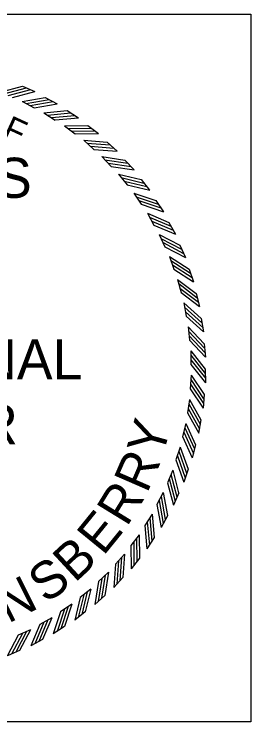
# Model space of a CAD drawing. Extents: x 164 to 3385, y 68 to 2119.
# Drawn here: x 3177.5 to 3264.9, y 441.7 to 702.4 of the extents above; entities that cross this region are included whole.
import ezdxf

# ---------------------------------------------------------------- set-up
doc = ezdxf.new("R2010")
doc.units = 0
doc.layers.add('R_No Plot', color=7, linetype='Continuous')
doc.layers.add('STAMP', color=7, linetype='Continuous')

msp = doc.modelspace()

# ---------------------------------------------------------------- linework, layer by layer
at = {"layer": 'R_No Plot'}
msp.add_lwpolyline([(3004.12, 702.45), (3264.86, 702.45), (3264.86, 441.7), (3004.12, 441.7)], close=True, dxfattribs=at)
at = {"layer": 'STAMP'}
for p, q in [((3180.63, 675.94), (3185.2, 673.98)), ((3180.56, 670.27), (3184.96, 667.94)), ((3189.04, 671.77), (3193.44, 669.45)), ((3188.5, 666.13), (3192.7, 663.44)), ((3197.07, 666.93), (3201.26, 664.25)), ((3196.07, 661.35), (3200.03, 658.32)), ((3204.68, 661.44), (3208.64, 658.42)), ((3203.22, 655.96), (3206.92, 652.62)), ((3211.81, 655.34), (3215.5, 652)), ((3209.9, 650), (3213.31, 646.36)), ((3218.41, 648.67), (3221.82, 645.04)), ((3216.07, 643.51), (3219.17, 639.6)), ((3224.44, 641.48), (3227.53, 637.58)), ((3221.68, 636.53), (3224.44, 632.38)), ((3229.85, 633.81), (3232.61, 629.67)), ((3226.69, 629.11), (3229.11, 624.74)), ((3234.61, 625.73), (3237.02, 621.37)), ((3231.08, 621.3), (3233.12, 616.75)), ((3238.69, 617.28), (3240.73, 612.74)), ((3234.8, 613.16), (3236.46, 608.45)), ((3242.06, 608.52), (3243.72, 603.83)), ((3237.84, 604.74), (3239.11, 599.91)), ((3244.69, 599.51), (3245.96, 594.7)), ((3240.17, 596.09), (3241.04, 591.18)), ((3246.57, 590.32), (3247.43, 585.42)), ((3241.78, 587.28), (3242.24, 582.31)), ((3247.68, 581), (3248.14, 576.05)), ((3242.66, 578.37), (3242.71, 573.38)), ((3248.02, 571.63), (3248.07, 566.65)), ((3242.8, 569.42), (3242.44, 564.44)), ((3247.59, 562.25), (3247.22, 557.29)), ((3242.2, 560.48), (3241.43, 555.55)), ((3246.38, 552.95), (3245.6, 548.03)), ((3240.87, 551.63), (3239.69, 546.78)), ((3238.8, 542.91), (3237.23, 538.18)), ((3244.41, 543.78), (3243.23, 538.94)), ((3241.68, 534.8), (3240.11, 530.07)), ((3236.03, 534.4), (3234.07, 529.81)), ((3232.56, 526.15), (3230.22, 521.74)), ((3238.23, 526.07), (3236.27, 521.5)), ((3228.42, 518.2), (3225.73, 514)), ((3234.06, 517.66), (3231.73, 513.26)), ((3223.64, 510.63), (3220.61, 506.67)), ((3229.22, 509.63), (3226.53, 505.44)), ((3218.25, 503.48), (3214.91, 499.78)), ((3223.73, 502.02), (3220.71, 498.06)), ((3212.29, 496.8), (3208.65, 493.39)), ((3217.63, 494.89), (3214.29, 491.2)), ((3205.8, 490.63), (3201.89, 487.53)), ((3210.96, 488.29), (3207.33, 484.88)), ((3198.82, 485.02), (3194.67, 482.26)), ((3191.4, 480.01), (3187.03, 477.59)), ((3203.77, 482.26), (3199.87, 479.17)), ((3183.59, 475.63), (3179.04, 473.58)), ((3196.1, 476.85), (3191.96, 474.09)), ((3188.02, 472.09), (3183.66, 469.68)), ((3179.57, 468.01), (3175.03, 465.97))]:
    msp.add_line(p, q, dxfattribs=at)
for points in [[(3172.29, 673.74), (3180.62, 675.94)], [(3173.76, 673.09), (3182.09, 675.29)], [(3175.36, 672.45), (3183.69, 674.65)], [(3176.88, 671.78), (3185.21, 673.98)], [(3180.55, 670.27), (3189.03, 671.77)], [(3181.96, 669.51), (3190.44, 671.01)], [(3183.5, 668.73), (3191.98, 670.24)], [(3184.96, 667.94), (3193.44, 669.45)], [(3188.49, 666.13), (3197.06, 666.93)], [(3189.83, 665.25), (3198.41, 666.05)], [(3191.31, 664.35), (3199.88, 665.15)], [(3192.69, 663.45), (3201.27, 664.25)], [(3196.06, 661.35), (3204.67, 661.44)], [(3197.32, 660.37), (3205.94, 660.45)], [(3198.72, 659.35), (3207.33, 659.44)], [(3200.03, 658.33), (3208.64, 658.42)], [(3203.21, 655.96), (3211.8, 655.34)], [(3204.39, 654.88), (3212.98, 654.25)], [(3205.7, 653.75), (3214.29, 653.12)], [(3206.92, 652.62), (3215.51, 652)], [(3209.89, 650), (3218.4, 648.67)], [(3210.98, 648.82), (3219.49, 647.49)], [(3212.19, 647.59), (3220.7, 646.26)], [(3213.31, 646.37), (3221.82, 645.04)], [(3216.06, 643.51), (3224.43, 641.48)], [(3217.04, 642.25), (3225.41, 640.22)], [(3218.15, 640.91), (3226.52, 638.89)], [(3219.17, 639.61), (3227.54, 637.58)], [(3221.67, 636.53), (3229.84, 633.82)], [(3222.55, 635.19), (3230.72, 632.48)], [(3223.54, 633.77), (3231.71, 631.06)], [(3224.44, 632.38), (3232.62, 629.67)], [(3226.68, 629.11), (3234.61, 625.73)], [(3227.45, 627.7), (3235.37, 624.32)], [(3228.32, 626.21), (3236.24, 622.83)], [(3229.11, 624.75), (3237.03, 621.37)], [(3231.07, 621.3), (3238.68, 617.28)], [(3231.71, 619.84), (3239.33, 615.82)], [(3232.46, 618.28), (3240.07, 614.25)], [(3233.12, 616.76), (3240.74, 612.74)], [(3234.79, 613.16), (3242.05, 608.53)], [(3235.31, 611.65), (3242.57, 607.01)], [(3235.93, 610.03), (3243.18, 605.39)], [(3236.46, 608.46), (3243.72, 603.82)], [(3237.83, 604.74), (3244.68, 599.52)], [(3238.23, 603.19), (3245.08, 597.97)], [(3238.7, 601.52), (3245.55, 596.3)], [(3239.11, 599.92), (3245.96, 594.7)], [(3240.17, 596.1), (3246.56, 590.33)], [(3240.43, 594.51), (3246.83, 588.75)], [(3240.77, 592.82), (3247.16, 587.05)], [(3241.04, 591.18), (3247.44, 585.41)], [(3241.78, 587.29), (3247.68, 581.01)], [(3241.91, 585.69), (3247.81, 579.41)], [(3242.11, 583.97), (3248, 577.7)], [(3242.24, 582.32), (3248.14, 576.04)], [(3242.66, 578.38), (3248.02, 571.63)], [(3242.66, 576.77), (3248.02, 570.03)], [(3242.71, 575.05), (3248.07, 568.3)], [(3242.71, 573.39), (3248.07, 566.64)], [(3242.8, 569.42), (3247.58, 562.26)], [(3242.58, 566.1), (3247.36, 558.94)], [(3242.67, 567.83), (3247.45, 560.66)], [(3242.44, 564.45), (3247.22, 557.28)], [(3241.93, 558.91), (3246.11, 551.38)], [(3242.2, 560.49), (3246.37, 552.96)], [(3241.43, 555.56), (3245.61, 548.03)], [(3241.7, 557.19), (3245.88, 549.66)], [(3240.86, 551.64), (3244.4, 543.78)], [(3240.1, 548.39), (3243.64, 540.54)], [(3240.47, 550.08), (3244.01, 542.23)], [(3239.69, 546.79), (3243.23, 538.93)], [(3238.8, 542.92), (3241.68, 534.8)], [(3237.77, 539.75), (3240.65, 531.64)], [(3238.28, 541.41), (3241.16, 533.29)], [(3237.23, 538.19), (3240.11, 530.07)], [(3235.38, 532.94), (3237.58, 524.61)], [(3236.03, 534.41), (3238.22, 526.08)], [(3234.07, 529.82), (3236.27, 521.49)], [(3234.74, 531.34), (3236.94, 523.01)], [(3231.8, 524.74), (3233.3, 516.26)], [(3232.56, 526.15), (3234.06, 517.67)], [(3230.23, 521.74), (3231.73, 513.26)], [(3231.02, 523.2), (3232.52, 514.72)], [(3227.54, 516.87), (3228.34, 508.3)], [(3228.42, 518.21), (3229.22, 509.64)], [(3225.74, 514.01), (3226.53, 505.43)], [(3226.64, 515.39), (3227.44, 506.82)], [(3222.66, 509.38), (3222.74, 500.76)], [(3223.64, 510.64), (3223.73, 502.03)], [(3220.62, 506.67), (3220.71, 498.06)], [(3221.64, 507.98), (3221.72, 499.37)], [(3218.25, 503.49), (3217.63, 494.9)], [(3216.04, 501), (3215.41, 492.41)], [(3217.17, 502.31), (3216.54, 493.72)], [(3214.91, 499.78), (3214.29, 491.19)], [(3211.11, 495.72), (3209.78, 487.21)], [(3212.29, 496.81), (3210.96, 488.3)], [(3208.66, 493.39), (3207.33, 484.88)], [(3209.88, 494.51), (3208.55, 486)], [(3205.8, 490.64), (3203.77, 482.27)], [(3203.2, 488.55), (3201.17, 480.18)], [(3204.53, 489.66), (3202.51, 481.29)], [(3198.82, 485.03), (3196.11, 476.86)], [(3201.89, 487.53), (3199.87, 479.16)], [(3196.06, 483.16), (3193.35, 474.99)], [(3197.48, 484.15), (3194.76, 475.98)], [(3191.4, 480.02), (3188.02, 472.09)], [(3194.67, 482.26), (3191.96, 474.08)], [(3187.04, 477.59), (3183.66, 469.67)], [(3188.5, 478.38), (3185.12, 470.46)], [(3189.99, 479.25), (3186.61, 471.33)], [(3182.13, 474.99), (3178.1, 467.37)], [(3183.59, 475.63), (3179.57, 468.02)], [(3179.05, 473.58), (3175.02, 465.96)], [(3180.57, 474.24), (3176.54, 466.63)]]:
    msp.add_lwpolyline(points, dxfattribs=at)

# ---------------------------------------------------------------- texts
for s, height, rotation, p in [('F', 9.06, 335.3628, (3172.65, 657.06)), ('Y', 13.75, 74.5264, (3232.21, 538.87)), ('R', 13.75, 66.5008, (3226.54, 525.6)), ('R', 13.75, 58.4752, (3219.08, 513.25)), ('E', 13.75, 50.8144, (3210.41, 502.55)), ('B', 13.75, 42.7888, (3199.89, 492.68)), ('S', 13.75, 35.4928, (3189.21, 485.07)), ('N', 13.75, 26.7376, (3175.25, 477.81))]:
    msp.add_text(s, height=height, rotation=rotation, dxfattribs=at).set_placement(p)
for s, height, p in [('ARKANSAS', 14.78, (3076.4, 634.77)), ('PROFESSIONAL', 14.7798, (3048.95, 567.88)), ('ENGINEER', 14.78, (3075.69, 543.95))]:
    msp.add_text(s, height=height, dxfattribs=at).set_placement(p)

doc.saveas('drawing.dxf')
